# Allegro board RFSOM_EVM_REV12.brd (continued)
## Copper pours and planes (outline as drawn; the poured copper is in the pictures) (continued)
DGND on ART05: 154.28,145.34 407.26,145.34 407.26,-33.98 154.28,-33.98 ; 10 cut-outs
DGND on POWER07: 154.28,145.34 407.26,145.34 407.26,-33.98 154.28,-33.98 ; 14 cut-outs
DGND on POWER08: 154.28,145.34 407.26,145.34 407.26,-33.98 154.28,-33.98 ; 9 cut-outs
DGND on ART10: 154.28,145.34 407.26,145.34 407.26,-33.98 154.28,-33.98 ; 11 cut-outs
DVDDL on BOTTOM: 377.02,63.58 377.02,62.83 376.35,62.16 376.35,58.08 376.23,57.96 374.3,57.96 374.17,58.09 374.17,60.03 374.33,60.19 374.66,60.19 374.94,60.46 374.94,62.43 376.28,63.78 376.82,63.78
VBUS on ART03: 403.77,-3.74 400.62,-6.89 393.56,-6.89 392.94,-6.26 392.94,0.21 394.87,2.13 394.87,9.8 393.65,11.02 393.65,16.97 394.24,17.57 403.21,17.57 403.77,17.02
VCC_1V8_FT on BOTTOM: 387.67,7.51 389.9,7.51 390.16,7.26 390.16,5.69 389.77,5.3 387.99,5.3 387.56,5.73 387.56,7.4
VCC_1V8_FT on ART05: 379.41,7.6 390.95,7.6 391.99,6.56 391.99,-2.28 390.77,-3.51 379.22,-3.51 378.39,-2.67 378.39,6.58
VCC_3V3_FT on TOP: 391.97,8.2 392.86,8.2 393.02,8.03 393.02,6.27 392.86,6.11 391.06,6.11 390.94,6.24 390.94,6.95 391.12,7.13 391.7,7.13 391.89,7.31 391.89,8.11
VCC_3V3_FT on BOTTOM: 392.49,8.1 394.02,8.1 394.66,7.45 394.66,2.3 394.56,2.2 393.8,2.2 393.62,2.38 393.62,3.42 393.14,3.9 393.14,5.51 392.34,6.31 392.34,7.94
VCC_3V3_FT on ART03: 375.11,-6.89 374.36,-6.14 374.36,17.04 374.91,17.59 392.77,17.59 393,17.37 393,11.06 394.48,9.57 394.48,2.26 392.4,0.17 392.4,-6.25 391.75,-6.89
VCC_5V on TOP: 229.4,117.44 230.55,116.3 230.55,105.91 229.63,104.99 223.48,104.99 221.71,103.22 221.71,89.98 222.19,89.5 229.3,89.5 229.91,90.11 229.91,95.39 233.21,98.69 239.89,98.69 243.86,102.66 243.86,119.07 243.25,119.67 243.25,121.66 242.86,122.04 242.26,122.04 242.1,121.88 242.1,120.94 241.85,120.69 240.99,120.69 240.86,120.56 240.86,119.62 240.65,119.42 239.69,119.42 239.44,119.67 239.44,121.68 239.38,121.73 239.35,121.73 238.97,122.11 238.17,122.11 235.55,119.5 235.24,119.5 235.12,119.62 235.12,121.91 234.94,122.09 234.46,122.09 231.74,119.37 231.23,119.37 231.02,119.57 231.02,122.45 230.74,122.74 229.63,122.74 229.4,122.5
VCC_5V on BOTTOM: 385.29,38.05 385.83,38.05 386.03,38.25 386.03,39.95 385.83,40.16 385.29,40.16 385.17,40.03 385.17,38.18
VCC_5V on POWER07: 213.62,142.52 400.75,142.52 403.63,139.63 403.63,31.4 402.65,30.41 385.8,30.41 383.6,32.61 383.6,71.75 383.59,71.83 383.55,71.89 380.88,74.56 380.82,74.6 380.75,74.61 333.38,74.61 333.3,74.6 333.24,74.56 330.57,71.89 330.53,71.83 330.52,71.75 330.52,36.27 330.01,35.77 270.94,35.77 218.45,-16.71 218.45,-31.47 217.29,-32.63 199.28,-32.63 198.39,-31.74 198.39,-29.65 198.44,-29.6 198.44,-21.69 230.86,10.73 230.86,73.28 229.47,74.68 226.47,74.68 226.42,74.63 219.34,74.63 212.61,81.37 212.61,141.51 ; 4 cut-outs
VCC_12V on TOP: 222.46,131.8 227.94,131.8 228.44,131.3 228.44,118.43 228.02,118.02 223.04,118.02 222.22,118.83 222.22,131.56
VCC_12V on TOP: 368.6,6.45 368.6,41.15 367.79,41.96 359.89,41.96 359.28,41.35 359.28,5.79 360.26,4.81 366.96,4.81
VCC_12V on TOP: 290.52,120.06 303.79,120.06 305.61,118.23 306.21,118.23 306.65,117.79 306.65,114.52 306.19,114.05 290.39,114.05 289.79,114.66 289.79,119.32
VCC_12V on TOP: 246.15,129.02 249.01,129.02 249.5,128.54 249.5,119.56 248.72,118.78 245.77,118.78 244.95,119.59 244.95,121.36 244.26,122.04 243.56,122.04 243.56,122.95 243.61,122.95 243.61,126.43 244.37,126.43 244.95,127.02 244.95,127.83
VCC_12V on POWER08: 222.14,142.41 400.01,142.41 401.58,140.85 401.58,-27.42 396.56,-32.44 201.66,-32.44 200.6,-31.38 200.6,-22 204.55,-18.06 245.61,-18.06 245.61,89.51 221.45,113.68 221.45,141.72 ; 15 cut-outs
VCCO_89 on TOP: 322.39,108.77 326.43,108.77 326.69,108.51 326.69,104.34 326.5,104.15 322.51,104.15 322.24,104.41 322.24,108.61
VCCO_89 on BOTTOM: 328.47,109.14 329.18,108.43 329.18,89.41 328.42,88.65 319.15,88.65 318.62,89.18 318.62,108.38 319.38,109.14
VCCO_501 on TOP: 313.05,108.77 317.09,108.77 317.35,108.51 317.35,104.34 317.15,104.15 313.16,104.15 312.89,104.41 312.89,108.61
VCCO_501 on ART03: 312.78,108.2 311.76,107.19 311.76,91.72 313.46,90.02 324.05,90.02 324.51,90.47 324.51,107.85 324.15,108.2
VCCO_502 on TOP: 317.72,108.77 321.76,108.77 322.02,108.51 322.02,104.34 321.83,104.15 317.83,104.15 317.56,104.41 317.56,108.61
VCCO_502 on ART10: 317.86,108.97 328.93,108.97 329.29,108.61 329.29,89.28 328.7,88.7 318.08,88.7 317.63,89.15 317.63,108.74
VDD33 on BOTTOM: 378.74,60.45 378.96,60.22 379.62,60.22 380.18,60.78 381.89,60.78 382.04,60.93 382.04,61.72 381.87,61.89 380.98,61.89 380.78,61.68 378.9,61.68 378.74,61.52
VDDH on ART03: 385.22,72.01 374.02,72.01 373.62,71.61 373.62,56.83 374.44,56.01 384.07,56.01 384.81,56.74 384.81,60.02 383.14,61.68 383.14,65.62 382.14,66.62 382.14,68.12 382.29,68.27 383.21,68.27 385.67,70.73 385.67,71.56
(no net) on TOP: 359.31,46.66 359,46.96 359,48.89 358.6,49.3 358.6,56.59 359.13,57.12 364.77,57.12 365.4,56.49 365.4,49.56 364.52,48.67 364.52,47.17 364.01,46.66
INTVCC1 on ART10: 230.28,127.99 244.58,127.99 245.08,127.48 245.08,124.64 244.53,124.08 230.05,124.08 229.49,124.64 229.49,127.2
SFP_VCCRX on TOP: 361.67,130.99 356.72,130.99 356.46,130.73 356.46,129.46 356.72,129.21 361.67,129.21 361.92,129.46 361.92,130.73
SFP_VCCRX on ART05: 360.02,133.36 360.27,133.62 370.27,133.62 370.31,133.58 370.31,129.72 369.86,129.27 360.61,129.27 360.02,129.86
SFP_VCCTX on TOP: 361.67,126.88 356.72,126.88 356.46,127.13 356.46,128.4 356.72,128.66 361.67,128.66 361.92,128.4 361.92,127.13
SFP_VCCTX on ART05: 360.65,128.83 360.02,128.19 360.02,125.15 360.27,124.89 369.95,124.89 370.34,125.28 370.34,128.65 370.15,128.83
USB_5V on TOP: 386.77,40.36 388.21,40.36 388.7,40.84 388.7,43.46 388.06,44.09 386.38,44.09 386.23,43.94 386.23,43.38 386.26,43.36 386.89,43.36 387.02,43.23 387.02,42.67 386.79,42.44 386.59,42.44 386.49,42.34 386.49,40.64
USB_5V on BOTTOM: 386.92,44.68 386.92,44.3 385.75,43.13 385.75,41.5 386.08,41.17 389.13,41.17 389.13,42.7 389.05,42.77 388.75,42.77 388.01,43.51 388.01,44.88 387.12,44.88
USB_5V on ART10: 388.63,43.61 389.08,43.16 389.08,34.21 390.28,33 393,33 393.4,32.6 393.4,29.44 393.02,29.06 386.74,29.06 385.88,29.92 385.88,43.18 386.31,43.61
N22363073 on BOTTOM: 389.31,45.06 390.88,45.06 391.44,45.62 391.44,49.02 391.87,49.45 392.86,49.45 392.87,49.45 394.19,49.45 394.44,49.2 394.44,47.8 394.69,47.55 395.45,47.55 395.83,47.93 395.83,49.83 394.61,51.05 389.84,51.05 389.05,50.27 389.05,45.31
N22363075 on TOP: 396.16,33.68 397.41,34.92 397.41,38.86 396.52,39.75 395.33,39.75 392.35,36.78 392.35,33.78 392.46,33.68
N22363075 on BOTTOM: 398.63,36.5 400,37.87 400,51.94 399.01,52.93 395.5,52.93 395.02,52.45 395.02,51.26 396.49,49.78 396.49,40.11 395.05,38.66 395.05,36.83 395.38,36.5
N22363103 on BOTTOM: 389.23,43.33 389.64,43.33 390.02,42.95 390.02,39.67 390.27,39.42 395.33,39.42 396.09,40.18 396.09,41.83 395.83,42.09 394.69,42.09 394.06,41.45 392.53,41.45 391.49,42.49 391.49,44.27 390.96,44.81 389.28,44.81 389.1,44.63 389.1,43.46
N22481429 on TOP: 368.78,1.91 375.44,1.91 376.61,0.74 376.61,-5.82 382.22,-11.43 395.76,-11.43 402.54,-18.21 402.54,-23.72 401.93,-24.33 397.21,-24.33 396.57,-23.7 396.57,-19.71 395.16,-18.3 374.48,-18.3 372.31,-16.13 372.31,-11.1 368.21,-7 368.21,1.33
N22481433 on TOP: 395.35,-19.53 396.04,-20.22 396.04,-26.06 395.3,-26.8 368.33,-26.8 367.51,-25.98 367.51,-21.67 367.67,-21.51 369.7,-21.51 371.68,-19.53
N22481513 on TOP: 366.09,1.91 366.65,1.35 366.65,-6.86 365.51,-8 359.64,-8 359.33,-7.7 359.33,1.44 359.8,1.91
N22481513 on BOTTOM: 306.35,144.25 306.6,143.99 306.6,19.13 308.81,16.92 365.07,16.92 366.93,15.06 366.93,-6.96 366.07,-7.82 359.28,-7.82 358.17,-6.71 358.17,8.71 356.84,10.03 299.87,10.03 298.75,11.15 298.75,135.79 299.06,136.09 302.49,136.09 302.74,136.35 302.74,140.23 302.34,140.64 298.63,140.64 298.07,141.2 298.07,143.94 298.37,144.25
N22481513 on ART05: 298.63,144.5 310.7,144.5 311.74,143.45 311.74,1.21 314.17,-1.22 367.39,-1.22 367.64,-1.47 367.64,-10.11 367.13,-10.62 297.54,-10.62 296.27,-9.35 296.27,134.72 297.66,136.12 302.28,136.12 302.74,136.58 302.74,140.23 302.34,140.64 298.63,140.64 298.07,141.2 298.07,143.94
N22481515 on TOP: 369.9,-9.42 370.71,-10.24 370.71,-18.03 370.26,-18.49 363.53,-18.49 362.65,-17.61 362.65,-10.17 363.4,-9.42
N22481515 on BOTTOM: 367.59,-13.77 367.59,-18.75 367.26,-19.08 298.1,-19.08 291.69,-12.67 291.69,138.61 293.19,140.11 301.9,140.11 302.34,139.67 302.34,136.88 301.96,136.5 298.68,136.5 298.37,136.19 298.37,-6.91 304.75,-13.28 367.1,-13.28
N22481515 on ART05: 367.59,-23.11 366.62,-24.08 282.42,-24.08 280.99,-22.65 280.99,138.71 282.39,140.11 301.9,140.11 302.34,139.67 302.34,136.88 301.96,136.5 297.03,136.5 295.88,135.36 295.88,-9.51 297.38,-11 367.24,-11 367.59,-11.35
N22533342 on ART03: 230,127.84 230.17,128.02 243.43,128.02 243.71,127.74 243.71,126.03 243.39,125.71 230.32,125.71 230,126.03
N22533342 on ART05: 243.23,127.99 243.51,127.71 243.51,127.15 243.1,126.75 229.9,126.75 229.72,126.92 229.72,127.56 230.15,127.99
N22533693 on ART03: 230.23,129.44 242.04,129.44 242.27,129.21 242.27,128.35 242.06,128.14 230.1,128.14 229.95,128.3 229.95,129.16
N22533693 on ART05: 243.23,129.26 243.51,128.98 243.51,128.42 243.1,128.02 229.9,128.02 229.72,128.19 229.72,128.83 230.15,129.26
N22535757 on TOP (solid shape): 365.4,56.49 365.4,49.56 364.52,48.67 364.52,47.17 364.01,46.66 359.31,46.66 359,46.96 359,48.89 358.83,49.07 358.83,49.09 358.76,49.29 358.6,49.43 358.6,56.59 359.13,57.12 364.77,57.12
N22535954 on TOP: 312.62,117.32 330.96,117.32 331.34,116.94 331.34,110.19 330.91,109.75 312.85,109.75 312.52,110.08 312.52,117.22

Small or netless copper shapes (teardrops, artwork), in the pictures only: 66 on TOP

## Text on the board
Ref Des/Assembly Bottom: MRF8 V1.0 ADB_CENTER
Package Geometry/Pastemask Bottom: MRF8 V1.0 PASTEMASK BOTTOM
User.Comments: MRF8 V1.0 SOLDMASK BOTTOM | CR_UNNAMED_12 | CR_1_10
Ref Des/Assembly Top: MRF8 V1.0 ADT_CENTER
Package Geometry/Pastemask Top: MRF8 V1.0 PASTEMASK TOP
Ref Des/Silkscreen Top: 2 | 4 | M.2_SSD
PANEL: MRF8 V1.0 PANEL
DIMENSION: 15 | 14 | 13 | 12 | 11 | 10 | POWER_LED | FAN_POWER_12V | AW | J22 | J23 | 1 | J26 | 20 | P8 | P9 | LED4 | J50 | LED3 | 9 | J49 | 8 | 7 | 6 | LED2 | 5 | J47 | 4 | 3 | 2 | LED1 | J46 | J21 | TRIGGER | J24 | PPS | J48 | J13 | JFA6 | SP1 | Switch | JFA4 | JFA5 | 39 | A | P4 | P3 | JFA2 | U1 | JFA1 | JFA3 | J10 | J18 | J19 | J40 | J17 | SWC2 | P6 | P7 | J31
BODY_CENTER: J16 | J15 | J14 | J13 | J12 | J11 | J10 | J9 | J8 | J7 | J4 | J6 | J5 | J3 | J2 | J1 | D25 | R321 | C74 | C53 | C44 | C35 | C71 | C68 | C65 | C59 | C50 | C47 | C41 | C38 | C32 | C77 | C62 | C56 | R316 | R90 | R83 | R79 | R75 | R62 | R87 | R82 | R71 | R66 | R58 | R54 | R53 | R50 | R49 | R42 | R41 | R38 | R33 | R29 | R94 | R91 | R86 | R78 | R70 | R46 | R45 | R65 | R61 | R57 | R37 | R32 | R74 | D24 | C72 | C66 | C63 | C48 | C78 | C76 | C75 | C73 | C69 | C67 | C64 | C60 | C58 | C57 | C55 | C54 | C51 | C42 | C39 | C70 | C52 | C46 | C45 | C33 | C61 | C49 | C40 | C37 | C36 | C34 | C31 | C43 | R318 | R315 | R214 | J46 | 10 | D22 | R219 | R215 | C312 | R222 | R325 | R218 | C319 | J48 | R217 | C315 | C309 | 1 | R324 | C310 | R330 | R329 | R220 | R210 | C293 | C297 | R216 | D10 | C311 | J45 | FB44 | FB45 | R308 | R309 | R226 | J42 | C343 | C183 | J34 | U36 | C348 | R306 | C5 | U61 | R225 | C346 | C332 | FB36 | J35 | C456 | C147 | C340 | CM211 | J38 | RM132 | J43 | C337 | U35 | J37 | C181 | C156 | C338 | C339 | R208 | C289 | R333 | C408 | C404 | C403 | R203 | C20 | C21 | C23 | C24 | C25 | C26 | C19 | C22 | CM227 | RM143 | RM144 | C406 | C92 | C91 | C96 | C95 | C93 | C94 | C90 | C89 | CM228 | EC15 | C195 | C196 | CM226 | R271 | CM186 | C444 | C445 | UM14 | 2 | CM221 | CM188 | U19 | 3 | RM72 | RM71 | CM187 | D3 | D2 | D1 | J36 | R256 | CM176 | D14 | CM175 | CM173 | R281 | R276 | D19 | Q4 | D20 | R250 | RM52 | CM170 | R255 | R257 | R249 | D15 | R248 | R121 | CM171 | C282 | R258 | R263 | R192 | R259 | R264 | R266 | R267 | R261 | R262 | U29 | R260 | R265 | C285 | C283 | R193 | EC13 | C254 | J21 | R169 | R331 | R332 | C274 | C276 | FB18 | FB19 | R147 | FB6 | C216 | C215 | U39 | U40 | U41 | U38 | U42 | U43 | C453 | FB42 | C370 | C351 | C354 | C355 | C349 | C358 | C365 | R235 | R237 | R238 | R229 | R239 | R242 | R162 | R163 | C451 | D5 | C361 | R146 | R148 | FB7 | FB8 | C360 | C367 | U26 | C378 | C235 | FB41 | R159 | R160 | R158 | C229 | C232 | R230 | C231 | D13 | FB10 | U44 | C372 | C371 | R135 | R133 | C226 | C211 | R145 | C227 | C228 | FB9 | C363 | J40 | J17 | 14 | 13 | 12 | 11 | UM3 | UM4 | UM10 | UM9 | UM1 | UM2 | U53 | UM7 | UM8 | H3 | H7 | H14 | H42 | H15 | H12 | H11 | H20 | H22 | H32 | H33 | H19 | H28 | H29 | H17 | H39 | H26 | H35 | H41 | J50 | U7 | U5 | U4 | U2 | U16 | U13 | U12 | U11 | U9 | U8 | U6 | U3 | U17 | U15 | U14 | U10 | 4 | 6 | R85 | R81 | R77 | R64 | R89 | R73 | R68 | R60 | R56 | R52 | R44 | R40 | R35 | R31 | R93 | R48 | R92 | R88 | R84 | R80 | R76 | R67 | R63 | R72 | R59 | R55 | R51 | R43 | R39 | R34 | R30 | R47 | J49 | J30 | H9 | H13 | H23 | H24 | H10 | H21 | H30 | H31 | H34 | H18 | H27 | H16 | H38 | H40 | H25 | H36 | H37 | R313 | D23 | J47 | R311 | R212 | Q10 | X6 | R211 | R213 | C295 | C294 | C304 | C303 | R310 | J29 | C298 | C296 | ID3 | C318 | R323 | H8 | C317 | C316 | J52 | C460 | C461 | C330 | 15 | R221 | C313 | X5 | Q14 | C314 | R322 | EC3 | EC7 | R328 | C300 | J51 | C299 | R326 | C302 | J39 | C301 | R327 | U33 | U1 | D26 | U62 | C308 | C307 | C458 | C306 | C457 | C455 | C454 | C305 | FB39 | FB38 | EC19 | CM208 | CM206 | 5 | 7 | 8 | 9 | UM16 | U34 | RM108 | RM107 | CM207 | C334 | C335 | C336 | 16 | 17 | C333 | 18 | FB37 | 19 | R307 | 20 | RM124 | CM216 | FB43 | 21 | R223 | C341 | C342 | 22 | 23 | 24 | A | 25 | UM17 | 26 | CM212 | 27 | CM195 | J44 | 28 | CM192 | 29 | CM202 | CM213 | RM85 | CM193 | 30 | CM204 | RM93 | X4 | 31 | RM99 | CM203 | 32 | CM215 | R224 | RM95 | CM201 | 33 | UM15 | RM75 | 34 | CM205 | RM98 | FB22 | 35 | CM199 | RM73 | 36 | CM198 | C538 | CM191 | RM100 | 37 | CM200 | C537 | RM77 | RM88 | CM196 | 38 | RM101 | 39 | C133 | RM84 | RM92 | C | E | G | J | L | N | R | U | W | AA | AC | AE | AG | AJ | AL | AN | AR | AU | AW | RM89 | B | D | F | H | K | M | P | T | V | Y | AB | AD | AF | AH | AK | AM | AP | AT | AV | RM103 | J28 | H2 | U32 | FB23 | C81 | C433 | R202 | EC8 | C281 | C287 | R282 | R201 | C280 | R288 | R123 | FB4 | H6 | U50 | RM49 | RM138 | RM57 | R122 | RM125 | FB3 | RM63 | RM128 | RM59 | CM218 | J33 | RM120 | U20 | RM39 | CM220 | R291 | D18 | CM185 | EC10 | EC1 | RM62 | RM137 | Y2 | Q7 | CM219 | C427 | X3 | RM37 | CM183 | RM113 | UM18 | CM225 | RM64 | RM136 | C432 | CM184 | EC4 | EC9 | RM41 | CM223 | RM109 | C418 | EC5 | C417 | EC2 | CM182 | RM65 | C414 | C411 | CM222 | RM134 | Q3 | Q2 | Q1 | CM181 | RM48 | RM111 | CM224 | RM56 | CM178 | RM131 | RM53 | CM179 | J32 | EC6 | RM67 | RM135 | CM180 | RM66 | RM129 | R301 | C389 | C383 | C388 | C381 | RM121 | R298 | Q8 | U47 | Q9 | R275 | R280 | U52 | R253 | C533 | C535 | U30 | U31 | C534 | C536 | U51 | C401 | C400 | C409 | UM13 | C416 | D4 | C410 | C415 | U46 | C394 | C395 | C379 | C380 | C386 | C385 | FB20 | R138 | FB21 | SP1 | BAT1 | Q6 | Q5 | EC17 | EC16 | C284 | R137 | R140 | U21 | C207 | R195 | R143 | R197 | C208 | J27 | R142 | R198 | EC12 | EC11 | R199 | D16 | D17 | U48 | U49 | R194 | C391 | R200 | R141 | U23 | R196 | C397 | C398 | X2 | C392 | R166 | H5 | C253 | U28 | EC14 | C258 | C266 | C259 | C267 | D9 | R167 | C243 | C240 | C244 | C245 | C246 | U63 | FB15 | FB12 | FB16 | FB17 | FB13 | FB14 | C247 | C260 | C270 | C272 | C262 | C264 | C268 | C238 | C248 | ID1 | C239 | C251 | C252 | C249 | C250 | J23 | J22 | R155 | R156 | R151 | R149 | R150 | R234 | R236 | R232 | R233 | Y1 | C352 | C353 | C356 | C350 | C359 | C366 | R153 | D21 | C374 | C376 | J26 | C369 | U24 | C373 | EC18 | X1 | R161 | R246 | C214 | U25 | C357 | U45 | U37 | C233 | R244 | FB40 | C362 | R243 | ID2 | Y3 | U27 | U18 | FB11 | J41 | J18 | C230 | D7 | D6 | J19 | U22 | D12 | D11 | SWC4 | SWC3 | SWC2 | H1 | H4 | J31 | SWC1 | UM12 | UM11 | UM5 | UM6 | U58 | J24 | J25 | U60 | OBLOGE VIA112X60MIL | + | BAR  CODE | MRF8 V1.0
User.17: FIGURE | FINISHED_SIZE | 10.0 | 17.0 | 20.0 | 28.0 | 30.0 | 33.0 | 34.0 | 39.37 | 40.0 | 41.0 | 44.0 | 48.0 | 52.0 | 60.0 | 65.0 | 71.0 | 91.0 | 99.0 | 125.0 | 138.0 | 150.0 | 43.0 | 57.0 | 61.0 | 63.0 | 126.0 | 62.99x23.62 | 82.68x23.62 | 112.0x60.0 | DRILL CHART: TOP to BOTTOM | ALL UNITS ARE IN MILS | PLATED | NON-PLATED | QTY | 6924 | 5 | 64 | 9 | 40 | 10 | 25 | 4 | 45 | 22 | 85 | 2 | 6 | 46 | 8 | 3 | 1
User.20: NOTES: | - MNC_LAYER: MUST-NOT-CUT-LAYER | - MAX_DEPTH: DEPTH FROM START LAYER TO THE | SURFACE OF MUST-NOT-CUT-LAYER | - MFG_STUB : MANUFACTURING STUB LENGTH | FIGURE | BD_SIZE | 10.0 | MNC_LAYER | GND04 | BACKDRILL: BOTTOM to ART05 | ALL UNITS ARE IN MILS | MAX_DEPTH | 51.0 | MFG_STUB | - | QTY | 60
